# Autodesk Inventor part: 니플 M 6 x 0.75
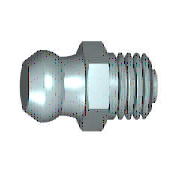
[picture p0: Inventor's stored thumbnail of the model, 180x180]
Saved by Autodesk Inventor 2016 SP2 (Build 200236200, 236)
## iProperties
IsCustomPart: 1
Created: 2012-02
Part Number: 니플 M 6 x 0.75
Material: 강철, 연강
Description: 윤활 니플, 원추 유형 A
Document SubType Name: Modeling
Standard: JIS B 1575
Designer: mduedu
Standards Organization: JIS
Language: ko-KR
Size Designation: MT 6 x 0.75
Categories: <MemberInstance><Categories><Category DisplayName="기타 부품" InternalName="5aa15e00-363f-49f2-933f-16f664388e3f" Mnemonic="OTHER"><Category DisplayName="그리스 부속품" I
Density: 1 g/cm^3
Appearance: 강철
Author: mduedu
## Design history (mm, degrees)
sketch "스케치1"
  geometry: L1 (-8.8, 0)-(-8.8, 2.4); L2 (-8.8, 2.4)-(-7.335, 3.202); L3 (-8.8, 0)-(4.7, 0); L4 (4.7, 0)-(4.7, 1.5); L5 (4.7, 1.5)-(4, 1.5); L6 (4, 1.5)-(4, 3); L7 (4, 3)-(0, 3); L8 (-11.5, 0)-(7.4, 0) reference; L9 (0, -1.733)-(0, 10.398) reference; L10 (-3, 3.5)-(0, 3.5); L11 (0, 3.5)-(0, 3); A1 r 3.3 centre (-6.535, 0) between (-4.789, 2.8) and (-7.335, 3.202); A2 r 6 centre (-6.053, 8.665) between (-4.789, 2.8) and (-3, 3.5)
  constraints: 18 end point, 5 perpendicular, 4 point on circle, 2 centre point, 2 parallel, 2 point on line, 1 collinear, 1 vertical
  dimensions: "d0" = 13.5 distance between parallel lines of L1 L4 (= GL); "d1" = 5.6 diameter of A1.start L3 (= KGB2); "d2" = 0.7 distance between parallel lines of L4 L6 (= PHH); "d3" = 3 diameter of L5 L3 (= 0.5 x NND); "d4" = 6 diameter of L7 L3 (= NND); "d5" = 6.6 dimension on A1 L3 (= KR); "d6" = 4.8 diameter of L1.end L3 (= KGB1); "d7" = 6 radius of A2 (= RBN); "d11" = 7 diameter of L10.start L3 (= SW); "d14" = 3 distance of L10.start L10.end (= KOH); "d15" = 4 distance between parallel lines of L6 L11 (= NLG); "d61" = 7.33505 distance from line of L9 L2.end (computed from KGB1, KR, PHH, GL, NLG, VERS); "d62" = 6.53505 distance from line of L9 A1.centre (computed from NLG, GL, PHH, KR, KGB1)
revolve "본체" sketch "스케치1" stored, may be unused: angle "d25" = 90 deg
sketch "스케치2"
  geometry: L1 (2.021, 3.5)-(4.041, 0); L2 (4.041, 0)-(2.021, -3.5); L3 (2.021, -3.5)-(-2.021, -3.5); L4 (-2.021, -3.5)-(-4.041, 0); L5 (-4.041, 0)-(-2.021, 3.5); L6 (-2.021, 3.5)-(2.021, 3.5); C1 r 3.5 at (0, 0) reference; 1 further point
  constraints: 12 end point, 1 coincident, 1 horizontal, 1 tangent, 11 other
extrude "머리" join sketch "스케치2" distance "d17" = 3 (= KOH); taper "d18" = 0 deg
sketch "스케치3"
  geometry: L1 (2.687, 4.041)-(3, 4.041); L2 (3, 4.041)-(3, 3.5); L3 (3, 3.5)-(2.687, 4.041); L4 (0.313, 4.041)-(0, 4.041); L5 (0, 4.041)-(0, 3.5); L6 (0, 3.5)-(0.313, 4.041); L7 (3.6, 0)-(-0.6, 0) reference; L8 (0, 4.041)-(0, 2.021) reference; L9 (0, 4.041)-(3, 4.041) reference; L10 (3, 3.031)-(3, 4.041) reference
  constraints: 12 end point, 4 collinear, 3 perpendicular, 1 horizontal
  dimensions: "d19" = 3.5 distance from line of L5.end L7 (= 0.5 x SW); "d20" = 3.5 distance from line of L2.end L7 (= 0.5 x SW); "d21" = 30 deg angle of L6 L5; "d22" = 30 deg angle of L2 L3
revolve "모따기1" sketch "스케치3" stored, may be unused: angle "d56" = 90 deg
body "Solid1"
fillet "모깎기1" dims "d8" = 0.2 (= RR)
feature "스레드1" dims "d9" = 3.53991 (= NLG - GAL), "d10" = 0
chamfer "모따기2" distance "d23" = 0.46009 (= -0.5 x GD1 + 0.5 x NND); stored, may be unused: angle "d24" = 45 deg, second distance "d59" = 0.46009 (= -0.5 x GD1 + 0.5 x NND)
other parameters: "NLG" = 4 [user parameter; used in 4 equation terms], "GL" = 13.5 [user parameter; used in 3 equation terms], "NND" = 6 [user parameter; used in 4 equation terms], "KGB1" = 4.8 [user parameter; used in 3 equation terms], "KGB2" = 5.6 [user parameter; used in 1 equation term], "VERS" = 0.8 [user parameter; used in 1 equation term], "KR" = 6.6 [user parameter; used in 3 equation terms], "RBN" = 6 [user parameter; used in 1 equation term], "SW" = 7 [user parameter; used in 3 equation terms], "KOH" = 3 [user parameter; used in 2 equation terms], "GAL" = 0.46009 (= 0.61345 x PTC) [user parameter; used in 1 equation term], "FAWI" = 45 deg [user parameter], "PHH" = 0.7 [user parameter; used in 3 equation terms], "GD1" = 5.07983 (= THREADDIA - 1.2269 x PTC) [user parameter; used in 2 equation terms], "RR" = 0.2 [user parameter; used in 1 equation term], "d12" = 0, "d13" = 0, "GUL" = 0.46009 (= 0.61345 x PTC) [user parameter], "TPU" = 13.33333 (computed from PTC) [user parameter], "DULO" = 1.5 [user parameter], "PTC" = 0.75 [user parameter; used in 4 equation terms], "GEL" = 4 [user parameter], "THREADDIA" = 6 [user parameter; used in 1 equation term], "TOA" = 30 deg [user parameter]
